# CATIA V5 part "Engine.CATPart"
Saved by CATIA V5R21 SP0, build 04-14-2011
Part number: Engine
Property "OverallLength": 5000 mm
Property "OverallDiameter": 3780 mm
Property "ChamberLength": 415 mm
Property "ChamberDiameter": 380 mm
Property "NozzleLength": 2085 mm
Property "NozzleThroatDiameter": 235 mm
Property "NozzleExitDiameter": 1430 mm
Property "SubEngineOffset": 1175 mm
Property "EngineOffset": 0 mm
Property "NumberSubEngines": 4
Property "NumberEngines": 4
Property "MultipleSubEngines": true
Property "MultipleEngines": false
Property "ZPosition": 0 mm
Bounding box of the stored display mesh (mm): x -1890.978 to 1890.978, y -1890.978 to 1890.978, z -5000.156 to 58.734
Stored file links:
  J:\Dropbox\Diplomarbeit\CATIA\Engine.CATPart
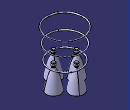
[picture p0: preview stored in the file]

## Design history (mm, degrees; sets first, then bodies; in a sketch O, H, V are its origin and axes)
Body1 (main body)
  Plane1 "ZPosition.Plane": type Offset, RefPlane xy-plane, Offset 0
  Sketch1 "EngineOffset.Sketch" on yz-plane, origin (0, 0, 0), H (0, 1, 0), V (0, 0, 1)
    line L1 (0, 0) -> (0, -5000)
    point P1 (0, 0)
    reference intersected line E1 through (0, 0) direction (-1, 0) from Plane1
    length L1 = 5000
    distance L1 V = 0
    vertical: L1 V
    coincidence: P1 E1
  Sketch2 on yz-plane, origin (0, 0, 0), H (0, 1, 0), V (0, 0, 1)
    point P1 (0, 0)
    construction line L1 (0, 0) -> (1175, 0)
    axis line L2 (1175, 0) -> (1175, -5000)
    construction line L3 (1175, -5000) -> (1890, -5000)
    construction line L4 (1890, -5000) -> (1905.6434, -5098.7688)
    point P6 (1175, -2500)
    line L5 (1175, -2500) -> (1327, -2500)
    point P7 (1365, -2500)
    line L6 (1365, -2538) -> (1365, -2749)
    point P8 (1365, -2749)
    construction line L7 (1175, -2915) -> (1292.5, -2915)
    point P9 (1175, -2915)
    arc A1 centre (1386.5, -2915) radius 94 from (1305.0936, -2868) to (1292.5, -2915) ccw
    point P11 (1386.5, -2915)
    arc A2 centre (1337.385, -2915) radius 44.885 from (1292.5, -2915) to (1298.5134, -2937.4425) ccw
    point P13 (1337.385, -2915)
    connectcurve C1
    connectcurve C2
    arc A3 centre (1327, -2538) radius 38 from (1327, -2500) to (1365, -2538) cw
    reference intersected line E1 through (0, 0) direction (-1, 0) from Plane1
    construction line L8 (1298.5134, -2937.4425) -> (1348.5134, -3024.045)
    construction line L9 (1305.0936, -2868) -> (1355.0936, -2781.3975)
    distance L3 L1 = 5000
    distance L2 V = 1175
    length L4 = 100
    angle L4 L2 = 9
    length L3 = 715
    length L7 = 117.5
    distance L7 L5 = 415
    distance L7 L3 = 2085
    radius A1 = 94
    radius A2 = 44.885
    distance P6 P7 = 190
    distance P7 P8 = 249
    radius A3 = 38
    length L8 = 100
    angle L8 L2 = 30
    length L9 = 100
    angle L9 L2 = 30
    horizontal: L1 H, L3 H, L5 H, L7 H
    vertical: L2 V, L6 V
    coincidence: P6 L2, P9 L2, P11 L7, P13 L7, L5 P7, L6 P7, P1 V, L1 E1
    tangency: A2 A1, A3 L5, A3 L6, L8 A2, L9 A1
  Shaft1 "SubEngine.Shaft": profile Sketch2, axis Sketch2.L2, angle 360, thin wall 1, second thickness 1
  CircPattern1 "SubEngine.CircPattern": of Shaft1, instances 4, angular step 90 {= 360.0*1 deg/CircPattern1.AngularNumber}, axis from Sketch1.L1
  Sketch3 on yz-plane, origin (0, 0, 0), H (0, 1, 0), V (0, 0, 1)
    circle A1 centre (1586.0429, -2915) radius 58.75
    point P1 (1586.0429, -2915)
    circle A2 centre (1708.5429, -1457.5) radius 58.75
    point P2 (1708.5429, -1457.5)
    construction line L1 (0, 0) -> (1890, 0)
    construction line L2 (1890, 0) -> (1645, -2915)
    construction line L3 (1645, -2915) -> (0, -2915)
    construction line L4 (0, -2915) -> (0, 0)
    construction line L5 (0, -1457.5) -> (1767.5, -1457.5)
    point P7 (0, -1457.5)
    point P8 (1767.5, -1457.5)
    circle A3 centre (1831.0429, 0) radius 58.75
    point P9 (1831.0429, 0)
    reference intersected line E1 through (0, 0) direction (-1, 0) from Plane1
    radius A2 = 58.75
    radius A1 = 58.75
    radius A3 = 58.75
    distance L4 V = 0
    length L1 = 1890
    length L4 = 2915
    length L3 = 1645
    distance L5 L1 = 1457.5 {= Sketch3.length(L4) /2}
    horizontal: L1 H, L3 H, L5 H
    vertical: L4 V
    tangency: A3 L2, A1 L2, A2 L2
    coincidence: P2 L5, P1 L3, L1 E1, P8 L2, P7 L4, P9 L1
  Shaft2 "EngineInfrastructure.Shaft": profile Sketch3, axis Sketch1.L1, angle 360
  CircPattern2 "Engine.CircPattern": of the body so far, instances 4, angular step 90 {= 360.0*1 deg/CircPattern2.AngularNumber}, axis from Z axis, deactivated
